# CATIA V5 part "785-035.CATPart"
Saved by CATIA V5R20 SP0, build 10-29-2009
Part number: 785-035
Revision: ANY
Definition: UNKNOWN
Nomenclature: 785-035
Source: Unknown
Bounding box of the stored display mesh (mm): x -17.5 to 17.5, y -20 to 9, z -132 to 18
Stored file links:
  C:\Users\Utente\Desktop\IO LAVORO\3D X SITO CF\X 3D SITO CF 27-09-2020\785\785-035.CATPart
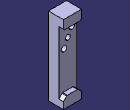
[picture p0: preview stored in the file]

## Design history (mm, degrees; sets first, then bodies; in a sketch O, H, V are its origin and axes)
Body1 "Smusso1" (main body)
  Solid1: solid without history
